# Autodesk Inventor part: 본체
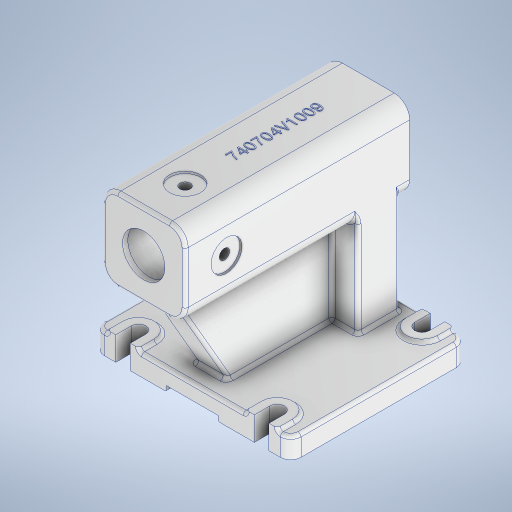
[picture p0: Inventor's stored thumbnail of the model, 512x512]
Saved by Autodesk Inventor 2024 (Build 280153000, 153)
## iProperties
Created: 2024-07
Part Number: 본체
Material: 알루미늄 6061
Document SubType Name: Modeling
Designer: com
Density: 2.7 g/cm^3
Appearance: 알루미늄 - 평지
Mass: 5575.12 g
Surface Area: 2201.89 cm^2
Volume: 2064.86 cm^3
Author: com
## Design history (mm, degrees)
sketch "스케치1"
  geometry: L1 (-85, -95)-(85, -95); L2 (85, -95)-(85, 95); L3 (85, 95)-(-85, 95); L4 (-85, 95)-(-85, -95); L5 (-85, -95)-(85, 95); L6 (85, -95)-(-85, 95); 1 further point
  constraints: 12 end point, 2 midpoint, 2 parallel, 1 horizontal, 1 perpendicular
  dimensions: "d0" = 170 distance of L3.end L2.end; "d1" = 190 distance of L2.end L1.end
extrude "돌출1" new body sketch "스케치1" distance "d2" = 20; taper "d3" = 0 deg
node "작업 평면1"
sketch "스케치3"
  geometry: L1 (-85, 95)-(-85, -95) reference; L2 (-85, 0)-(-75, 0); L3 (-75, 0)-(-75, -40); L4 (-75, -40)-(-35, -40); L5 (-35, -40)-(-35, -15); L6 (-35, -15)-(53.838, -15); L7 (53.838, -15)-(53.838, 0); L8 (53.838, 0)-(-75, 0); L9 (-35, 15)-(53.838, 15); L10 (53.838, 15)-(53.838, 0); L11 (-35, 40)-(-35, 15); L12 (-75, 40)-(-35, 40); L13 (-75, 0)-(-75, 40)
  constraints: 24 end point, 5 perpendicular, 4 symmetric about line, 2 horizontal, 1 midpoint, 1 point on line
  dimensions: "d9" = 10 distance of L2.start L2.end; "d10" = 40 distance of L2.end L3.end; "d11" = 40 distance of L3.end L4.end; "d12" = 25 distance of L4.end L5.end
sketch "스케치4"
  geometry: L1 (-132, 110)-(85, 110); L2 (85, 110)-(85, 190); L3 (85, 190)-(-132, 190); L4 (-132, 190)-(-132, 110); L5 (-132, 110)-(85, 190); L6 (85, 110)-(-132, 190); L7 (-85, 0)-(85, 0) reference; L8 (85, 0)-(85, 20) reference; 2 further points
  constraints: 12 end point, 2 midpoint, 2 parallel, 1 horizontal, 1 perpendicular
  dimensions: "d13" = 217 distance of L3.end L2.end; "d14" = 80 distance of L1.end L2.end; "d15" = 150 distance from line of L7 point (-23.5, 150)
extrude "돌출2" join sketch "스케치4" stored distance "d17" = 80; taper "d18" = 0 deg
extrude "돌출3" join sketch "스케치3" stored distance "d19" = 80; taper "d20" = 0 deg
sketch "스케치5"
  geometry: L1 (85, 20)-(-85, 20) reference; L2 (35, 110)-(-132, 110) reference; L3 (-132, 110)-(-105.8, 110); L4 (-117, 110)-(-65.038, 20); 2 further points
  constraints: 4 end point, 3 point on line
  dimensions: "d117" = 120 deg angle of L1 L4
sketch "스케치6"
  geometry: C1 r 20.5 at (-40, 40); 2 further points
  constraints: 1 centre point, 1 coincident
  dimensions: "d28" = 41 diameter of C1
extrude "돌출4" cut sketch "스케치6" extent not by distance; stored distance "d29" = 0; taper "d30" = 0 deg
sketch "스케치8"
  geometry: L1 (0, -133)-(0, 133) reference; L2 (85, -95)-(85, 95) reference; L3 (70, 74)-(85, 74); L4 (70, 60)-(85, 60); L5 (85, 74)-(85, 60); L6 (70, 82)-(85, 82); L7 (70, 52)-(85, 52); L8 (85, 82)-(85, 52); A1 r 15 centre (70, 67) between (55, 67) and (85, 67); A2 r 7 centre (70, 67) between (77, 67) and (63, 67); 2 further points
  constraints: 12 end point, 8 point on circle, 4 perpendicular, 4 point on line, 2 centre point, 2 collinear, 1 coincident, 1 midpoint, 1 tangent
  dimensions: "d49" = 67 vertical distance of A1.centre point (85, 0); "d110" = 15 distance from line of L5 A1.centre; "d111" = 14 diameter of A2; "d112" = 14 distance between parallel lines of L3 L4; "d113" = 7 distance from line of A1.centre L4
extrude "돌출6" cut sketch "스케치8" distance "d40" = 212; taper "d41" = 0 deg
extrude "돌출7" join sketch "스케치8" distance "d42" = 3; taper "d43" = 0 deg
fillet "모깎기1" dims "d53" = 15
fillet "모깎기6" dims "d62" = 3
fillet "모깎기2" dims "d83" = 3
sketch "스케치9"
  geometry: L1 (-5, 85)-(5, 85); L2 (5, 85)-(5, 35); L3 (5, 35)-(-5, 35); L4 (-5, 35)-(-5, 85); L5 (-5, 85)-(5, 35); L6 (5, 85)-(-5, 35); 1 further point
  constraints: 12 end point, 2 midpoint, 2 parallel, 1 horizontal, 1 perpendicular
  dimensions: "d55" = 10 distance of L2.end L3.end; "d56" = 50 distance of L1.end L2.end
extrude "돌출8" cut sketch "스케치9" extent not by distance; stored distance "d57" = 0; taper "d58" = 0 deg
fillet "모깎기3" dims "d59" = 10
fillet "모깎기4" dims "d60" = 3
fillet "모깎기5" dims "d61" = 3
sketch "스케치10"
  geometry: C1 r 20.5 at (37, 25) reference; C2 r 26 at (37, 25); 1 further point
  constraints: 1 centre point, 1 coincident
  dimensions: "d64" = 52 diameter of C2
extrude "돌출9" cut sketch "스케치10" distance "d65" = 212; taper "d66" = 0 deg
sketch "스케치11"
  geometry: 3 further points
hole "구멍1" sketch "스케치11" at (69, 25) diameter "d68" = 4.917; stored, may be unused: countersink angle "d72" = 90 deg, drill point angle "d74" = 118 deg; dims "d69" = 12, "d70" = 4, "d71" = 2, "d73" = 14
chamfer "모따기1" distance "d78" = 2; stored, may be unused: second distance "d79" = 2, angle "d80" = 30 deg
fillet "모깎기8" dims "d81" = 1
fillet "모깎기9" dims "d82" = 2
sketch "스케치12"
  geometry: C1 r 15 at (177, 25); 1 further point
  constraints: 1 centre point
  dimensions: "d85" = 30 diameter of C1
extrude "돌출10" cut sketch "스케치12" distance "d86" = 2; taper "d87" = 0 deg
sketch "스케치13"
  geometry: C1 r 15 at (0, 0) reference; 2 further points
  constraints: 1 coincident
hole "구멍2" sketch "스케치13" at (0, 0) diameter "d88" = 10.106; stored, may be unused: countersink angle "d92" = 90 deg, drill point angle "d94" = 118 deg; dims "d89" = 24, "d90" = 4, "d91" = 2, "d93" = 32.3
sketch "스케치14"
  geometry: L1 (0, 0)-(0, 50) reference; 2 further points
  constraints: 1 horizontal alignment, 1 other
  dimensions: "d101" = 90 distance from line of L1 point (90, 25)
feature "엠보싱1" sketch "스케치14" dims "d9" = 10, "d10" = 40, "d11" = 40, "d12" = 25, "d102" = 0.5, "d103" = 0
chamfer "모따기2" distance "d104" = 1; stored, may be unused: second distance "d105" = 2, angle "d106" = 45 deg
chamfer "모따기3" distance "d107" = 1; stored, may be unused: second distance "d108" = 2, angle "d109" = 45 deg
feature "리브2" dims "d118" = 1, "d119" = 30, "d120" = 0, "d121" = 0, "d122" = 1, "d123" = 1
fillet "모깎기10" dims "d124" = 3
feature "ʿ耀ˁ耀˃耀˅耀ˇ耀ˉ耀ˋ耀ˍ耀" dims "d0" = 170, "d1" = 190, "d2" = 20, "d3" = 0, "d9" = 10, "d10" = 40, "d11" = 40, "d12" = 25, "d13" = 217, "d14" = 80, "d15" = 150, "d17" = 80, "d18" = 0, "d19" = 80, "d20" = 0, "d28" = 41, "d29" = 0, "d30" = 0, "d40" = 212, "d41" = 0, "d42" = 3, "d43" = 0, "d49" = 67, "d50" = 20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
node "솔리드1"
pattern_linear "직사각형 패턴2" dims "d52" = 134
mirror "미러2"
pattern_circular "원형 패턴1" dims angle "d76" = 360 deg
pattern_circular "원형 패턴2" dims angle "d96" = 90 deg
pattern_circular "원형 패턴3" dims angle "d99" = 270 deg
feature "A9D066F2-1C7D-4E18-AEED-F7BC21143FA4" dims "d68" = 4.917, "d69" = 12, "d70" = 4, "d71" = 2, "d72" = 90 deg, "d73" = 14, "d74" = 118 deg
